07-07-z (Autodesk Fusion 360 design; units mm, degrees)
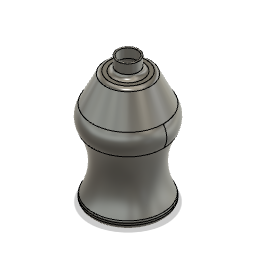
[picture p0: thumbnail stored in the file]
sketch "スケッチ1" plane through (0, 0, 0) normal (0, 1, 0) x axis (1, 0, 0)
  circle C1 centre (0, 0) radius 25
  point P1 (0, 0)
  point P2 (0, 0)
  coincident P1 P2
  dimension "d1" diameter C1 = 50
extrude "押し出し1" new body sketch "スケッチ1" along normal blind 5
work_plane "作業平面1" AlongDistance 20
sketch "スケッチ2" plane through (0, 25, 0) normal (0, 1, 0) x axis (1, 0, 0)
  circle C1 centre (0, 0) radius 20
  point P1 (0, 0)
  point P2 (0, 0)
  coincident P1 P2
  dimension "d5" diameter C1 = 40
work_plane "作業平面2" AlongDistance 20
sketch "スケッチ3" plane through (0, 45, 0) normal (0, 1, 0) x axis (1, 0, 0)
  circle C1 centre (0, 0) radius 25
loft "ロフト1" sketch "スケッチ2" + "スケッチ3"
work_plane "作業平面3" AlongDistance 15
sketch "スケッチ4" plane through (0, 60, 0) normal (0, 1, 0) x axis (1, 0, 0)
  circle C1 centre (0, 0) radius 25
sketch "スケッチ5" plane through (0, 0, 0) normal (0, 0, 1) x axis (1, 0, 0)
  line L1 (-25, 60) -> (25, 60)
  line L2 (25, 45) -> (-25, 45)
  arc A1 centre (-14.3816, 52.5) radius 13 clockwise from (-25, 45) to (-25, 60)
  arc A2 centre (14.3816, 52.5) radius 13 clockwise from (25, 60) to (25, 45)
  point P2 (-25, 60)
  point P9 (-25, 60)
  point P3 (-25, 45)
  point P10 (-25, 45)
  point P5 (25, 60)
  point P8 (25, 60)
  point P6 (25, 45)
  point P11 (25, 45)
  coincident P2 P9
  coincident P3 P10
  coincident P5 P8
  coincident P6 P11
  equal A1 A2
  dimension "d8" radius A1 = 13
sketch "スケッチ6" plane through (0, 0, 0) normal (1, 0, 0) x axis (0, 0, -1)
  line L1 (-25, 60) -> (25, 60)
  line L2 (25, 45) -> (-25, 45)
  arc A1 centre (-14.3816, 52.5) radius 13 clockwise from (-25, 45) to (-25, 60)
  arc A2 centre (14.3816, 52.5) radius 13 clockwise from (25, 60) to (25, 45)
  point P2 (-25, 60)
  point P9 (-25, 60)
  point P3 (-25, 45)
  point P10 (-25, 45)
  point P6 (25, 45)
  point P11 (25, 45)
  point P5 (25, 60)
  point P8 (25, 60)
  coincident P2 P9
  coincident P3 P10
  coincident P6 P11
  coincident P5 P8
  equal A1 A2
  dimension "d9" radius A1 = 13
loft "ロフト2" sketch "スケッチ4"
work_plane "作業平面4" AlongDistance 20
sketch "スケッチ7" plane through (0, 80, 0) normal (0, 1, 0) x axis (1, 0, 0)
  circle C1 centre (0, 0) radius 15
  point P1 (0, 0)
  point P2 (0, 0)
  coincident P1 P2
  dimension "d12" diameter C1 = 30
loft "ロフト3" sketch "スケッチ7"
sketch "スケッチ8" plane through (0, 80, 0) normal (0, 1, 0) x axis (-1, 0, 0)
  circle C1 centre (0, 0) radius 15
  circle C2 centre (0, 0) radius 7.5
  point P1 (0, 0)
  point P3 (0, 0)
  coincident P1 P3
  dimension "d13" diameter C2 = 15
extrude "押し出し2" add sketch "スケッチ8" profile of C2 along normal blind 10
fillet "フィレット1" radius 3
shell "シェル" innerThickness 1
fillet "フィレット2" radius 0.5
